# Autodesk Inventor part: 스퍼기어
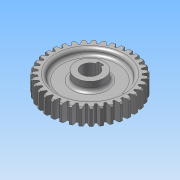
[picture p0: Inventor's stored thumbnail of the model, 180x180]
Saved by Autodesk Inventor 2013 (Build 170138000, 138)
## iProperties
Created: 2013-08
Part Number: 스퍼기어
Material: 강
Document SubType Name: Modeling
Designer: 한국산업디자인학원
Categories: <?xml version="1.0" encoding="UTF-16"?> <MemberInstance><Categories><FamilyTemplate><FamilyTemplateParameter ValueType="xs:double" Id="1" ObjectReferenceKey="da
Density: 1 g/cm^3
CustomPartVersion: 1
Author: 한국산업디자인학원
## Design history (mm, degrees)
sketch "Sketch1"
  geometry: C1 r 37 at (0, 0)
  constraints: 1 centre point
  dimensions: "d0" = 74 diameter of C1 (= da_da)
extrude "Extrusion1" new body sketch "Sketch1" distance "d1" = 15 (= da_b); taper "d2" = 0 deg
chamfer "모따기1" distance "d49" = 1; stored, may be unused: second distance "d50" = 2, angle "d51" = 45 deg
workplane "Work Plane2"
feature "피치 지름" dims "d4" = 10, "d5" = 0
workplane "Work Plane8"
workplane "Work Plane9"
feature "스퍼 기어" dims "da_b" = 15, "da_d" = 70, "da_aw" = 70, "da_da" = 74, "da_df" = 65, "da_dw" = 70, angle "da_beta" = 0 deg, "da_lefttooth" = 0, "da_righttooth" = 0
node "작업 평면11"
sketch "스케치3"
  geometry: C1 r 12.5 at (0, 0); 1 further point
  constraints: 1 centre point, 1 coincident
  dimensions: "d53" = 25 diameter of C1
extrude "돌출2" join sketch "스케치3" distance "d55" = 31; taper "d56" = 0 deg
sketch "스케치4"
  geometry: C1 r 12.5 at (0, 0) reference; C2 r 27.5 at (0, 0); A1 r 32.5 centre (0, 0) between (9.347, 31.127) and (7.941, 31.515) reference
  constraints: 1 centre point, 1 coincident
  dimensions: "d57" = 55 diameter of C2
extrude "돌출3" cut sketch "스케치4" distance "d59" = 5; taper "d60" = 0 deg
sketch "스케치5"
  geometry: C1 r 12.5 at (0, 0) reference; C2 r 27.5 at (0, 0); A1 r 36 centre (0, 0) between (-5.215, 35.62) and (-7.633, 35.181) reference
  constraints: 1 centre point, 1 coincident
  dimensions: "d61" = 55 diameter of C2
extrude "돌출4" cut sketch "스케치5" distance "d63" = 5; taper "d64" = 0 deg
sketch "스케치6"
  geometry: L1 (-2.5, 7.071)-(-2.5, 9.8); L2 (-2.5, 9.8)-(2.5, 9.8); L3 (2.5, 9.8)-(2.5, 7.071); C1 r 12.5 at (0, 0) reference; A1 r 7.5 centre (0, 0) between (-2.5, 7.071) and (2.5, 7.071); 1 further point
  constraints: 6 end point, 2 point on circle, 1 centre point, 1 coincident, 1 midpoint, 1 parallel, 1 perpendicular, 1 vertical, 1 vertical alignment
  dimensions: "d65" = 15 diameter of A1; "d67" = 5 distance of L1.end L2.end; "d68" = 17.3 dimension on A1 L2
extrude "돌출5" cut sketch "스케치6" stored distance "d69" = 5; taper "d70" = 0 deg
fillet "모깎기1" dims "d71" = 3
body "Solid1"
sketch "Sketch2"
  geometry: C1 r 37 at (0, 0) reference; C2 r 35 at (0, 0)
  constraints: 1 centre point, 1 coincident
  dimensions: "d3" = 70 diameter of C2 (= da_dw)
body "Srf1"
other parameters: "d17" = 0, "d34" = 0.8976 (computed from da_z), "d39" = 0, "d41" = 0, "d47" = 0, "d48" = 0, "d52" = 3
